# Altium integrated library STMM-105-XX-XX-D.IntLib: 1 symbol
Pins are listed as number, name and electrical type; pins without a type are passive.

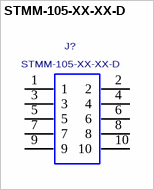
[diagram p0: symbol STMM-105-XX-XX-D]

## STMM-105-XX-XX-D
designator J?
2 MM TERMINAL STRIP ASSEMBLY, 10 PINS.; MANUFACTURER: SAMTEC
footprint STMM-105-XX-XX-D
pins: 1, 2, 3, 4, 5, 6, 7, 8, 9, 10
